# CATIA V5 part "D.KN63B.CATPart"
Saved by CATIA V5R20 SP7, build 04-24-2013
Part number: D.KN63B
Material "Nessuno"
Bounding box of the stored display mesh (mm): x -30.572 to 150.807, y -143.683 to 0, z -91.151 to 75.737
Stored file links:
  C:\Users\designer2\Desktop\Ottobre 2022\25-10-2022\04\Yori Evo 48V\D.KN63B.CATPart
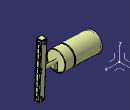
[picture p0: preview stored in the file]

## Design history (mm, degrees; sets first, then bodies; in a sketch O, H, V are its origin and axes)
AxisSystem1: origin (0, 0, 0), X (1, 0, 0), Y (0, 1, 0), Z (0, 0, 1)
Set1
  DatumSurface1
Body1 (main body), material "Nessuno"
